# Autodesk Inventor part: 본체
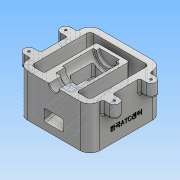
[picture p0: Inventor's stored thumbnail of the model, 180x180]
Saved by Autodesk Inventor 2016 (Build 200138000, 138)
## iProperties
Created: 2018-01
Part Number: 본체
Material: 알루미늄 6061
Document SubType Name: Modeling
Designer: Administrator
Density: 2.7 g/cm^3
Appearance: 알루미늄 - 평지
Mass: 994.563 g
Surface Area: 836.853 cm^2
Volume: 368.357 cm^3
Author: Administrator
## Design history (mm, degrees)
sketch "스케치1"
  geometry: L1 (-55, 55)-(55, 55); L2 (55, 55)-(55, -55); L3 (55, -55)-(-55, -55); L4 (-55, -55)-(-55, 55); L5 (-55, 55)-(55, -55); L6 (55, 55)-(-55, -55); 1 further point
  constraints: 12 end point, 2 midpoint, 2 parallel, 1 horizontal, 1 perpendicular
  dimensions: "d0" = 110 distance of L2.end L3.end; "d1" = 110 distance of L1.end L2.end
extrude "돌출1" new body sketch "스케치1" distance "d2" = 65; taper "d3" = 0 deg
sketch "스케치5"
  geometry: L1 (55, 55)-(-55, 55) reference; L2 (-55, 55)-(-55, -55) reference; L3 (-55, -55)-(55, -55) reference; L4 (55, -55)-(55, 55) reference; L5 (-45, 45)-(45, 45); L6 (45, 45)-(45, -45); L7 (45, -45)-(-45, -45); L8 (-45, -45)-(-45, 45); 1 further point
  constraints: 8 end point, 3 other
  dimensions: "d7" = 10 distance between parallel lines of L1 L5
extrude "돌출2" cut sketch "스케치5" stored distance "d8" = 65; taper "d9" = 0 deg
sketch "스케치6"
  geometry: L1 (-55, 0)-(-55, 65) reference; L2 (-55, 5.885)-(35, 30); L3 (35, 30)-(35, 65); L4 (45, 0)-(-45, 0) reference; L5 (55, 0)-(55, 65) reference; L6 (-45, 65)-(45, 65) reference; L7 (35, 65)-(-55, 65); L8 (45, 65)-(-45, 65) reference; 1 further point
  constraints: 6 end point, 2 point on line, 1 collinear, 1 parallel
  dimensions: "d12" = 105 deg angle of L2 L1; "d13" = 30 distance from line of L4 L2.end; "d14" = 20 distance between parallel lines of L5 L3
extrude "돌출4" join sketch "스케치6" stored distance "d15" = 50; taper "d16" = 0 deg
sketch "스케치7"
  geometry: L1 (-55, 0)-(-55, 65) reference; L2 (55, 65)-(-55, 65) reference; L3 (-55, 65)-(30, 65); L4 (-55, 65)-(-55, 72.5); L5 (-55, 72.5)-(-36, 72.5); L6 (-36, 72.5)-(-36, 81); L7 (-36, 81)-(-22, 81); L8 (-22, 81)-(-22, 85); L9 (-22, 85)-(25, 85); L10 (49.242, 64.927)-(49.242, 65); L11 (25, 85)-(25, 80); L12 (25, 80)-(30, 80); L13 (30, 80)-(30, 65); 1 further point
  constraints: 22 end point, 8 perpendicular, 2 vertical, 1 horizontal
  dimensions: "d17" = 15 diameter of L5 L2; "d18" = 32 diameter of L7 L2; "d19" = 40 diameter of L9 L2; "d20" = 30 diameter of L12 L2; "d21" = 19 distance of L4.end L5.end; "d22" = 14 distance of L6.end L7.end; "d23" = 47 distance of L8.end L9.end; "d24" = 5 distance of L11.end L12.end
revolve "회전1" sketch "스케치7" stored, may be unused: angle "d25" = 90 deg
sketch "스케치8"
  geometry: L1 (7.5, -55)-(55, -55) reference; L2 (55, -55)-(55, 55) reference; L3 (55, -20.5)-(65, -20.5); L4 (65, -20.5)-(65, -35.5); L5 (65, -35.5)-(55, -35.5); L6 (55, -35.5)-(55, -20.5); L7 (55, -20.5)-(65, -35.5); L8 (65, -20.5)-(55, -35.5); A1 r 7.5 centre (65, -28) between (65, -35.5) and (65, -20.5); 3 further points
  constraints: 12 end point, 4 midpoint, 2 parallel, 2 point on circle, 1 centre point, 1 horizontal, 1 perpendicular, 1 point on line
  dimensions: "d26" = 27 distance from line of point (60, -28) L1; "d27" = 7.5 radius of A1; "d28" = 10 distance between parallel lines of L4 L2
extrude "돌출5" join sketch "스케치8" distance "d29" = 20; taper "d30" = 0 deg
sketch "스케치10"
  geometry: A1 r 7.5 centre (65, -28) between (65, -35.5) and (65, -20.5) reference; A2 r 7.5 centre (65, 28) between (65, 20.5) and (65, 35.5) reference; A3 r 7.5 centre (-65, 28) between (-65, 35.5) and (-65, 20.5) reference; A4 r 7.5 centre (-65, -28) between (-65, -20.5) and (-65, -35.5) reference; 1 further point
sketch "스케치11"
  geometry: L1 (-55, 0)-(-55, 65) reference; L2 (35, 30)-(-45, 8.564) reference; L3 (20, 31.157)-(-55, 11.061); L4 (-22, 65)-(25, 65) reference; L5 (-17, 53.034)-(20, 53.034); L6 (20, 53.034)-(20, 31.157); L7 (-17, 39.243)-(-17, 53.034); L8 (-17, 53.034)-(20, 31.157); L9 (20, 53.034)-(-17.572, 30.819); L10 (-17, 39.243)-(-55, 29.061); 4 further points
  constraints: 14 end point, 3 midpoint, 3 parallel, 3 point on line, 2 vertical alignment, 1 horizontal, 1 perpendicular
  dimensions: "d33" = 5 distance between parallel lines of L2 L3; "d36" = 37 distance between parallel lines of L6 L7; "d38" = 18 distance of L3.end L10.end; "d39" = 75 deg angle of L10 L1 (derived)
extrude "돌출6" cut sketch "스케치11" stored distance "d40" = 30; taper "d41" = 0 deg
fillet "모깎기1" dims "d42" = 1
hole "구멍1" sketch "스케치10" diameter "d44" = 3.242; stored, may be unused: countersink angle "d48" = 90 deg, drill point angle "d50" = 118 deg; dims "d45" = 9, "d46" = 4, "d47" = 2, "d49" = 11
fillet "모깎기3" dims "d51" = 5, "d52" = 15
fillet "모깎기4" dims "d53" = 3
fillet "모깎기5" dims "d54" = 3
fillet "모깎기6" dims "d55" = 3
chamfer "모따기1" distance "d56" = 1; stored, may be unused: second distance "d57" = 2, angle "d58" = 45 deg
chamfer "모따기2" distance "d59" = 1; stored, may be unused: second distance "d60" = 2, angle "d61" = 45 deg
fillet "모깎기7" dims "d62" = 3
fillet "모깎기8" dims "d63" = 3
sketch "스케치13"
  geometry: L1 (0, 80)-(0, 0) reference; L2 (-65, -15)-(0, -15) reference; 2 further points
  constraints: 1 other
  dimensions: "d64" = 55 distance from line of point (-20, 40) L2; "d65" = 20 distance from line of L1 point (-20, 40)
feature "엠보싱1" sketch "스케치13" dims "d0" = 110, "d1" = 110, "d66" = 0.5, "d67" = 0
fillet "모깎기9" dims "d68" = 3
fillet "모깎기12" dims "d71" = 3
fillet "모깎기13" dims "d72" = 3
fillet "모깎기15" dims "d74" = 3
fillet "모깎기16" dims "d75" = 3
fillet "모깎기17" dims "d76" = 3
node "솔리드1"
mirror "대칭1"
mirror "대칭2"
other parameters: "d34" = 18, "d35" = 75 deg (derived)
